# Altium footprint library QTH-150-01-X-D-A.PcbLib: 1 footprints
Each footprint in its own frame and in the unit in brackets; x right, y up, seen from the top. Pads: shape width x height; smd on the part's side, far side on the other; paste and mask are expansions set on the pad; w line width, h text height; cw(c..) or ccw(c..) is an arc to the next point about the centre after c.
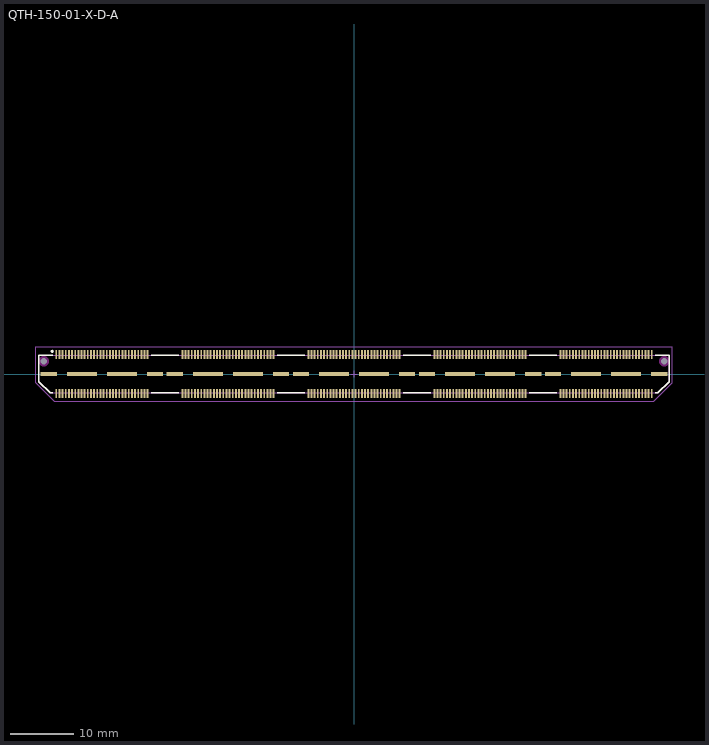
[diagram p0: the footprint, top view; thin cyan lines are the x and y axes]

## QTH-150-01-X-D-A [mm] "0.50mm pitch, 300 pin, high speed terminal strip"
height 4.27
pads (322):
  rect 0.3x1.45 smd mask+0: 1(-47.25,3.09) 2(-47.25,-3.09) 3(-46.75,3.09) 4(-46.75,-3.09) 5(-46.25,3.09) 6(-46.25,-3.09) 7(-45.75,3.09) 8(-45.75,-3.09) 9(-45.25,3.09) 10(-45.25,-3.09) 11(-44.75,3.09) 12(-44.75,-3.09) 13(-44.25,3.09) 14(-44.25,-3.09) 15(-43.75,3.09) 16(-43.75,-3.09) 17(-43.25,3.09) 18(-43.25,-3.09) 19(-42.75,3.09) 20(-42.75,-3.09) 21(-42.25,3.09) 22(-42.25,-3.09) 23(-41.75,3.09) 24(-41.75,-3.09) 25(-41.25,3.09) 26(-41.25,-3.09) 27(-40.75,3.09) 28(-40.75,-3.09) 29(-40.25,3.09) 30(-40.25,-3.09) 31(-39.75,3.09) 32(-39.75,-3.09) 33(-39.25,3.09) 34(-39.25,-3.09) 35(-38.75,3.09) 36(-38.75,-3.09) 37(-38.25,3.09) 38(-38.25,-3.09) 39(-37.75,3.09) 40(-37.75,-3.09) 41(-37.25,3.09) 42(-37.25,-3.09) 43(-36.75,3.09) 44(-36.75,-3.09) 45(-36.25,3.09) 46(-36.25,-3.09) 47(-35.75,3.09) 48(-35.75,-3.09) 49(-35.25,3.09) 50(-35.25,-3.09) 51(-34.75,3.09) 52(-34.75,-3.09) 53(-34.25,3.09) 54(-34.25,-3.09) 55(-33.75,3.09) 56(-33.75,-3.09) 57(-33.25,3.09) 58(-33.25,-3.09) 59(-32.75,3.09) 60(-32.75,-3.09) 61(-27.25,3.09) 62(-27.25,-3.09) 63(-26.75,3.09) 64(-26.75,-3.09) 65(-26.25,3.09) 66(-26.25,-3.09) 67(-25.75,3.09) 68(-25.75,-3.09) 69(-25.25,3.09) 70(-25.25,-3.09) 71(-24.75,3.09) 72(-24.75,-3.09) 73(-24.25,3.09) 74(-24.25,-3.09) 75(-23.75,3.09) 76(-23.75,-3.09) 77(-23.25,3.09) 78(-23.25,-3.09) 79(-22.75,3.09) 80(-22.75,-3.09) 81(-22.25,3.09) 82(-22.25,-3.09) 83(-21.75,3.09) 84(-21.75,-3.09) 85(-21.25,3.09) 86(-21.25,-3.09) 87(-20.75,3.09) 88(-20.75,-3.09) 89(-20.25,3.09) 90(-20.25,-3.09) 91(-19.75,3.09) 92(-19.75,-3.09) 93(-19.25,3.09) 94(-19.25,-3.09) 95(-18.75,3.09) 96(-18.75,-3.09) 97(-18.25,3.09) 98(-18.25,-3.09) 99(-17.75,3.09) 100(-17.75,-3.09) 101(-17.25,3.09) 102(-17.25,-3.09) 103(-16.75,3.09) 104(-16.75,-3.09) 105(-16.25,3.09) 106(-16.25,-3.09) 107(-15.75,3.09) 108(-15.75,-3.09) 109(-15.25,3.09) 110(-15.25,-3.09) 111(-14.75,3.09) 112(-14.75,-3.09) 113(-14.25,3.09) 114(-14.25,-3.09) 115(-13.75,3.09) 116(-13.75,-3.09) 117(-13.25,3.09) 118(-13.25,-3.09) 119(-12.75,3.09) 120(-12.75,-3.09) 121(-7.25,3.09) 122(-7.25,-3.09) 123(-6.75,3.09) 124(-6.75,-3.09) 125(-6.25,3.09) 126(-6.25,-3.09) 127(-5.75,3.09) 128(-5.75,-3.09) 129(-5.25,3.09) 130(-5.25,-3.09) 131(-4.75,3.09) 132(-4.75,-3.09) 133(-4.25,3.09) 134(-4.25,-3.09) 135(-3.75,3.09) 136(-3.75,-3.09) 137(-3.25,3.09) 138(-3.25,-3.09) 139(-2.75,3.09) 140(-2.75,-3.09) 141(-2.25,3.09) 142(-2.25,-3.09) 143(-1.75,3.09) 144(-1.75,-3.09) 145(-1.25,3.09) 146(-1.25,-3.09) 147(-0.75,3.09) 148(-0.75,-3.09) 149(-0.25,3.09) 150(-0.25,-3.09) 151(0.25,3.09) 152(0.25,-3.09) 153(0.75,3.09) 154(0.75,-3.09) 155(1.25,3.09) 156(1.25,-3.09) 157(1.75,3.09) 158(1.75,-3.09) 159(2.25,3.09) 160(2.25,-3.09) 161(2.75,3.09) 162(2.75,-3.09) 163(3.25,3.09) 164(3.25,-3.09) 165(3.75,3.09) 166(3.75,-3.09) 167(4.25,3.09) 168(4.25,-3.09) 169(4.75,3.09) 170(4.75,-3.09) 171(5.25,3.09) 172(5.25,-3.09) 173(5.75,3.09) 174(5.75,-3.09) 175(6.25,3.09) 176(6.25,-3.09) 177(6.75,3.09) 178(6.75,-3.09) 179(7.25,3.09) 180(7.25,-3.09) 181(12.75,3.09) 182(12.75,-3.09) 183(13.25,3.09) 184(13.25,-3.09) 185(13.75,3.09) 186(13.75,-3.09) 187(14.25,3.09) 188(14.25,-3.09) 189(14.75,3.09) 190(14.75,-3.09) 191(15.25,3.09) 192(15.25,-3.09) 193(15.75,3.09) 194(15.75,-3.09) 195(16.25,3.09) 196(16.25,-3.09) 197(16.75,3.09) 198(16.75,-3.09) 199(17.25,3.09) 200(17.25,-3.09) 201(17.75,3.09) 202(17.75,-3.09) 203(18.25,3.09) 204(18.25,-3.09) 205(18.75,3.09) 206(18.75,-3.09) 207(19.25,3.09) 208(19.25,-3.09) 209(19.75,3.09) 210(19.75,-3.09) 211(20.25,3.09) 212(20.25,-3.09) 213(20.75,3.09) 214(20.75,-3.09) 215(21.25,3.09) 216(21.25,-3.09) 217(21.75,3.09) 218(21.75,-3.09) 219(22.25,3.09) 220(22.25,-3.09) 221(22.75,3.09) 222(22.75,-3.09) 223(23.25,3.09) 224(23.25,-3.09) 225(23.75,3.09) 226(23.75,-3.09) 227(24.25,3.09) 228(24.25,-3.09) 229(24.75,3.09) 230(24.75,-3.09) 231(25.25,3.09) 232(25.25,-3.09) 233(25.75,3.09) 234(25.75,-3.09) 235(26.25,3.09) 236(26.25,-3.09) 237(26.75,3.09) 238(26.75,-3.09) 239(27.25,3.09) 240(27.25,-3.09) 241(32.75,3.09) 242(32.75,-3.09) 243(33.25,3.09) 244(33.25,-3.09) 245(33.75,3.09) 246(33.75,-3.09) 247(34.25,3.09) 248(34.25,-3.09) 249(34.75,3.09) 250(34.75,-3.09) 251(35.25,3.09) 252(35.25,-3.09) 253(35.75,3.09) 254(35.75,-3.09) 255(36.25,3.09) 256(36.25,-3.09) 257(36.75,3.09) 258(36.75,-3.09) 259(37.25,3.09) 260(37.25,-3.09) 261(37.75,3.09) 262(37.75,-3.09) 263(38.25,3.09) 264(38.25,-3.09) 265(38.75,3.09) 266(38.75,-3.09) 267(39.25,3.09) 268(39.25,-3.09) 269(39.75,3.09) 270(39.75,-3.09) 271(40.25,3.09) 272(40.25,-3.09) 273(40.75,3.09) 274(40.75,-3.09) 275(41.25,3.09) 276(41.25,-3.09) 277(41.75,3.09) 278(41.75,-3.09) 279(42.25,3.09) 280(42.25,-3.09) 281(42.75,3.09) 282(42.75,-3.09) 283(43.25,3.09) 284(43.25,-3.09) 285(43.75,3.09) 286(43.75,-3.09) 287(44.25,3.09) 288(44.25,-3.09) 289(44.75,3.09) 290(44.75,-3.09) 291(45.25,3.09) 292(45.25,-3.09) 293(45.75,3.09) 294(45.75,-3.09) 295(46.25,3.09) 296(46.25,-3.09) 297(46.75,3.09) 298(46.75,-3.09) 299(47.25,3.09) 300(47.25,-3.09)
  rect 2.55x0.65 smd mask+0: 301(-48.445,0) 304(-31.555,0) 305(-28.445,0) 308(-11.555,0) 309(-8.445,0) 312(8.445,0) 313(11.555,0) 316(28.445,0) 317(31.555,0) 320(48.445,0)
  rect 4.7x0.65 smd mask+0: 302(-43.175,0) 303(-36.825,0) 306(-23.175,0) 307(-16.825,0) 310(-3.175,0) 311(3.175,0) 314(16.825,0) 315(23.175,0) 318(36.825,0) 319(43.175,0)
  round 0.5 hole 1 unplated mask+0: 321(-49.24,2.03) 322(49.24,2.03)
Top Overlay:
  circle w0.25: c-47.9,3.6 r0.125
  lines w0.2: -47.8,-3 -48.2,-3 -50,-1.2 -50,3 -47.8,3 ; -32.2,-3 -27.8,-3 ; -32.2,3 -27.8,3 ; -12.2,-3 -7.8,-3 ; -12.2,3 -7.8,3 ; 7.8,-3 12.2,-3 ; 7.8,3 12.2,3 ; 27.8,-3 32.2,-3 ; 27.8,3 32.2,3 ; 47.8,-3 48.2,-3 50,-1.2 50,3 47.8,3
Keep-Out Layer:
  pour cut-out: 50.047,2.03 50.019,2.239 49.939,2.433 49.811,2.601 49.643,2.729 49.449,2.809 49.24,2.837 49.031,2.809 48.837,2.729 48.669,2.601 48.541,2.433 48.461,2.239 48.433,2.03 48.461,1.821 48.541,1.627 48.669,1.459 48.837,1.331 49.031,1.251 49.24,1.223 49.449,1.251 49.643,1.331 49.811,1.459 49.939,1.627 50.019,1.821
  pour cut-out: -48.433,2.03 -48.461,2.239 -48.541,2.433 -48.669,2.601 -48.837,2.729 -49.031,2.809 -49.24,2.837 -49.449,2.809 -49.643,2.729 -49.811,2.601 -49.939,2.433 -50.019,2.239 -50.047,2.03 -50.019,1.821 -49.939,1.627 -49.811,1.459 -49.643,1.331 -49.449,1.251 -49.24,1.223 -49.031,1.251 -48.837,1.331 -48.669,1.459 -48.541,1.627 -48.461,1.821
Mechanical 12:
  lines w0.001: -50,-1.2 -50,3 50,3 50,-1.2 48.2,-3 -48.2,-3 -50,-1.2
Mechanical 13:
  lines w0.1: -50,-1.2 -50,3 50,3 50,-1.2 48.2,-3 -48.2,-3 -50,-1.2
  text ".Designator" at 0.127,-0.127 h1.52
Mechanical 15:
  lines w0.05: -0.5,0 0.5,0 ; 0,-0.5 0,0.5 ; -50.5,-1.4 -50.5,4.3 50.5,4.3 50.5,-1.4 47.6,-4.3 -47.6,-4.3 -50.5,-1.4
